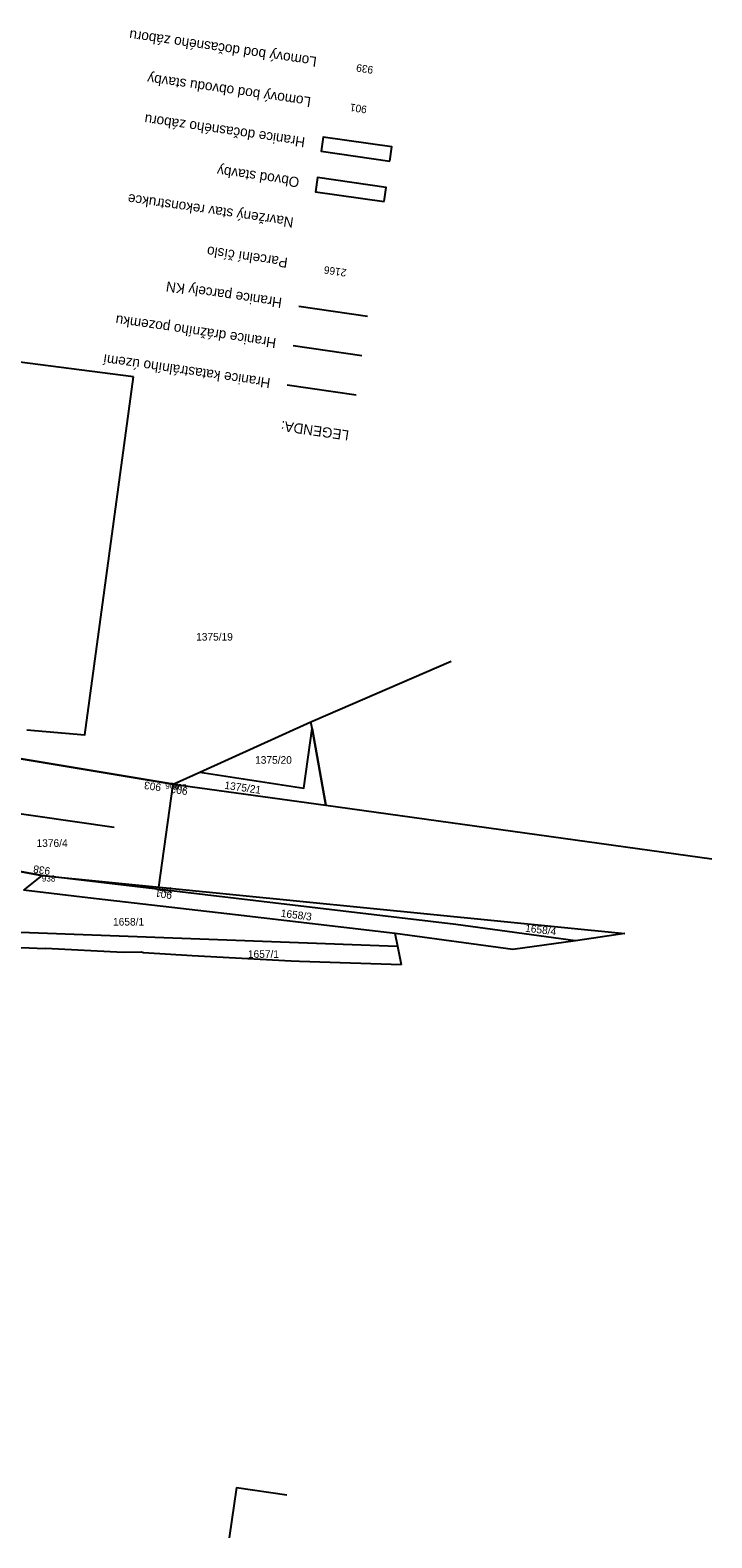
# Model space of a CAD drawing. Extents: x -757895 to -757311, y -1060303 to -1059942.
# Drawn here: x -757445.9 to -757311.4, y -1060302.6 to -1060005.3 of the extents above; entities that cross this region are included whole.
import ezdxf

# ---------------------------------------------------------------- set-up
doc = ezdxf.new("R2010")
doc.units = 0
for name, color, linetype in [('Dočasné zábory', 7, 'Continuous'), ('Legenda 1', 7, 'Continuous'), ('Legenda 2', 7, 'Continuous'), ('Level 53', 7, 'Continuous'), ('Obvod stavby', 7, 'Continuous'), ('Vrstva 1', 7, 'Continuous'), ('Vrstva 53', 7, 'Continuous'), ('Vrstva 55', 7, 'Continuous'), ('Vrstva 57', 7, 'Continuous'), ('Vrstva 60', 7, 'Continuous')]:
    doc.layers.add(name, color=color, linetype=linetype)

msp = doc.modelspace()

# ---------------------------------------------------------------- linework, layer by layer
at = {"layer": 'Dočasné zábory'}
msp.add_lwpolyline([(-757374.91, -1060031.14), (-757374.51, -1060028.36), (-757388.07, -1060026.4), (-757388.47, -1060029.18), (-757374.91, -1060031.14)], dxfattribs=at)
at = {"layer": 'Legenda 1'}
for q in [(-757406.6, -1060302.59), (-757395.28, -1060294.12)]:
    msp.add_line((-757405.18, -1060292.69), q, dxfattribs=at)
at = {"layer": 'Level 53'}
msp.add_line((-757380.46, -1060069.54), (-757394.02, -1060067.58), dxfattribs=at)
at = {"layer": 'Obvod stavby'}
for points in [[(-757376.05, -1060039.14), (-757375.65, -1060036.36), (-757389.21, -1060034.4), (-757389.61, -1060037.18), (-757376.05, -1060039.14)], [(-757420.49, -1060174.29), (-757417.66, -1060153.97), (-757419.22, -1060153.71), (-757450.04, -1060148.6), (-757493.93, -1060141.33), (-757496.99, -1060140.91), (-757515.4, -1060138.37), (-757520.85, -1060137.84), (-757523.49, -1060137.59), (-757525.99, -1060137.35), (-757528.28, -1060137.03), (-757533.01, -1060136.32), (-757534.03, -1060136.19), (-757535.86, -1060133.35), (-757568.62, -1060130.44), (-757606.63, -1060125.23), (-757624.32, -1060124.22), (-757624.54, -1060126.42), (-757639.93, -1060124.17), (-757687.19, -1060114.38)], [(-757686.64, -1060138.39), (-757635.44, -1060145.86), (-757634.26, -1060145.96), (-757632.1, -1060146.3), (-757543.88, -1060160.4), (-757542.9, -1060160.49), (-757535.01, -1060161.18), (-757533.6, -1060161.43), (-757526.21, -1060162.71), (-757513.1, -1060164.5), (-757470.38, -1060167.04), (-757443.58, -1060171.99), (-757420.49, -1060174.29)]]:
    msp.add_lwpolyline(points, dxfattribs=at)
at = {"layer": 'Vrstva 1'}
msp.add_line((-757429.32, -1060162.53), (-757720.62, -1060120.47), dxfattribs=at)
at = {"layer": 'Vrstva 53'}
for points in [[(-757687.19, -1060114.38), (-757639.93, -1060124.17), (-757624.54, -1060126.42), (-757624.32, -1060124.22), (-757612.89, -1060124.84), (-757606.63, -1060125.23), (-757568.62, -1060130.44), (-757535.86, -1060133.35), (-757534.03, -1060136.19), (-757533.01, -1060136.32), (-757528.28, -1060137.03), (-757525.99, -1060137.35), (-757523.49, -1060137.59), (-757520.85, -1060137.84), (-757515.4, -1060138.37), (-757496.99, -1060140.91), (-757493.93, -1060141.33), (-757450.04, -1060148.6), (-757417.66, -1060153.97), (-757412.43, -1060151.61), (-757391.89, -1060154.81), (-757390.25, -1060143), (-757387.56, -1060158.16)], [(-757328.56, -1060183.46), (-757338.29, -1060184.85), (-757361.91, -1060181.63), (-757443.58, -1060171.99), (-757470.38, -1060167.04), (-757513.1, -1060164.5), (-757526.21, -1060162.71), (-757533.6, -1060161.43), (-757535.01, -1060161.18), (-757542.9, -1060160.49), (-757543.88, -1060160.4), (-757632.1, -1060146.3), (-757634.26, -1060145.96), (-757635.44, -1060145.86), (-757686.64, -1060138.39), (-757693.18, -1060137.43), (-757732.62, -1060131.67), (-757793.56, -1060122.78), (-757866, -1060118.97)]]:
    msp.add_lwpolyline(points, dxfattribs=at)
at = {"layer": 'Vrstva 55'}
for p, q in [((-757379.32, -1060061.8), (-757392.88, -1060059.84)), ((-757425.51, -1060073.71), (-757474.75, -1060067.35)), ((-757381.6, -1060077.28), (-757395.16, -1060075.32)), ((-757412.43, -1060151.61), (-757390.54, -1060141.71)), ((-757390.25, -1060143), (-757390.54, -1060141.71)), ((-757387.56, -1060158.16), (-757390.25, -1060143)), ((-757450.04, -1060148.6), (-757417.66, -1060153.97)), ((-757417.66, -1060153.97), (-757412.43, -1060151.61)), ((-757417.66, -1060153.97), (-757387.56, -1060158.16)), ((-757387.56, -1060158.16), (-757311.39, -1060168.71)), ((-757443.58, -1060171.99), (-757447.18, -1060174.91)), ((-757443.58, -1060171.99), (-757328.56, -1060183.46)), ((-757373.35, -1060185.99), (-757373.86, -1060183.46)), ((-757350.67, -1060186.62), (-757373.86, -1060183.46)), ((-757328.56, -1060183.46), (-757338.29, -1060184.85)), ((-757457.81, -1060185.8), (-757442.84, -1060186.4)), ((-757427.56, -1060187.16), (-757442.84, -1060186.4)), ((-757372.63, -1060189.61), (-757373.35, -1060185.99)), ((-757338.29, -1060184.85), (-757350.67, -1060186.62)), ((-757423.99, -1060187.1), (-757427.56, -1060187.16)), ((-757372.63, -1060189.61), (-757392.78, -1060188.96))]:
    msp.add_line(p, q, dxfattribs=at)
for points in [[(-757446.57, -1060143.26), (-757435.09, -1060144.26), (-757425.51, -1060073.71)], [(-757390.54, -1060141.71), (-757390.04, -1060141.48), (-757362.82, -1060129.73)], [(-757412.43, -1060151.61), (-757391.89, -1060154.81), (-757390.25, -1060143)], [(-757513.1, -1060164.5), (-757470.38, -1060167.04), (-757443.58, -1060171.99)], [(-757338.29, -1060184.85), (-757361.91, -1060181.63), (-757443.58, -1060171.99)], [(-757373.86, -1060183.46), (-757405.36, -1060179.78), (-757434.52, -1060176.38), (-757447.18, -1060174.91)], [(-757373.35, -1060185.99), (-757375.27, -1060185.92), (-757449.6, -1060183.18)], [(-757413.91, -1060187.83), (-757423.52, -1060187.25), (-757423.99, -1060187.1)], [(-757392.78, -1060188.96), (-757394.39, -1060188.87), (-757413.91, -1060187.83)]]:
    msp.add_lwpolyline(points, dxfattribs=at)
at = {"layer": 'Vrstva 60'}
for p, q in [((-757419.22, -1060153.71), (-757419.22, -1060153.71)), ((-757417.66, -1060153.97), (-757417.66, -1060153.97)), ((-757443.58, -1060171.99), (-757443.58, -1060171.99)), ((-757420.49, -1060174.29), (-757420.49, -1060174.29))]:
    msp.add_line(p, q, dxfattribs=at)

# ---------------------------------------------------------------- texts
at = {"layer": 'Dočasné zábory'}
msp.add_text('939', height=1.5, rotation=171.7882, dxfattribs=at).set_placement((-757378.11, -1060012.47))
at = {"layer": 'Legenda 2'}
for s, p in [('Lomový bod dočasného záboru', (-757389.25, -1060010.64)), ('Lomový bod obvodu stavby', (-757390.39, -1060018.56)), ('Hranice dočasného záboru', (-757391.54, -1060026.48)), ('Obvod stavby', (-757392.68, -1060034.39)), ('Navržený stav rekonstrukce', (-757393.82, -1060042.31)), ('Parcelní číslo', (-757394.97, -1060050.23)), ('Hranice parcely KN', (-757396.11, -1060058.15)), ('Hranice drážního pozemku', (-757397.25, -1060066.07)), ('Hranice katastrálního území', (-757398.39, -1060073.98)), ('LEGENDA:', (-757382.88, -1060084.29))]:
    msp.add_text(s, height=2, rotation=171.7882, dxfattribs=at).set_placement(p)
at = {"layer": 'Obvod stavby'}
for s, p in [('901', (-757379.36, -1060020.28)), ('903', (-757419.96, -1060153.92)), ('902', (-757414.72, -1060154.67)), ('938', (-757441.84, -1060170.44)), ('901', (-757417.79, -1060175.18))]:
    msp.add_text(s, height=1.5, rotation=171.7882, dxfattribs=at).set_placement(p)
at = {"layer": 'Vrstva 57'}
for s, rotation, p in [('2166', 171.7882, (-757383.4, -1060052.47)), ('1375/21', 352, (-757407.63, -1060154.9)), ('1658/3', 353, (-757396.51, -1060180.14)), ('1658/4', 353, (-757348.29, -1060183.06))]:
    msp.add_text(s, height=1.5, rotation=rotation, dxfattribs=at).set_placement(p)
for s, p in [('1375/19', (-757413.15, -1060125.69)), ('1375/20', (-757401.51, -1060149.97)), ('1376/4', (-757444.63, -1060166.36)), ('1658/1', (-757429.54, -1060181.87)), ('1657/1', (-757402.93, -1060188.24))]:
    msp.add_text(s, height=1.5, dxfattribs=at).set_placement(p)
at = {"layer": 'Vrstva 60'}
for s, p in [('903', (-757419.22, -1060154.91)), ('902', (-757417.66, -1060155.17)), ('938', (-757443.58, -1060173.19)), ('901', (-757420.49, -1060175.49))]:
    msp.add_text(s, height=1.2, dxfattribs=at).set_placement(p)

doc.saveas('drawing.dxf')
